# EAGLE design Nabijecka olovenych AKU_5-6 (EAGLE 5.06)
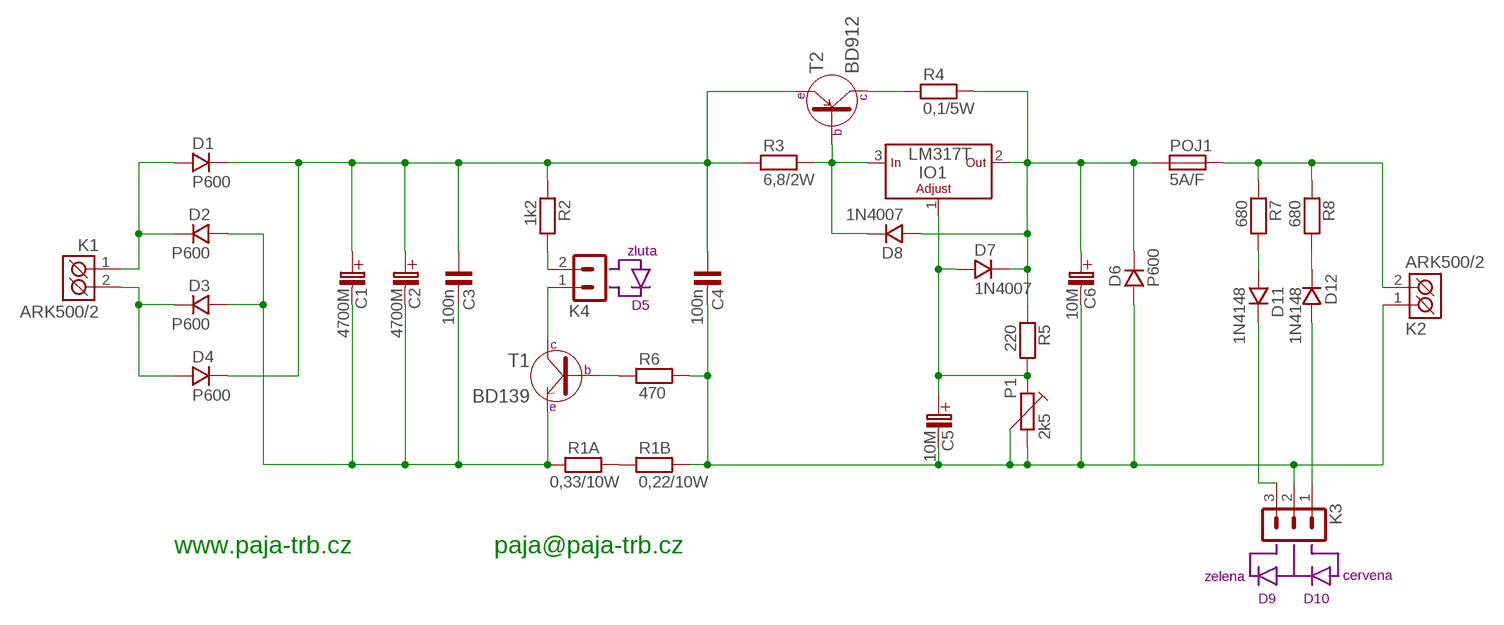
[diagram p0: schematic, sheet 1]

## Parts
C1  4700M  4700M/35V  [C_EL7,5+]
C2  4700M  4700M/35V  [C_EL7,5+]
C3  100n  C-KERAMIK_5  [C-5]
C4  100n  C-KERAMIK_5  [C-5]
C5  10M  10M/25V  [C_EL_2]
C6  10M  10M/25V  [C_EL_2]
D1  P600  [P6]
D2  P600  [P6]
D3  P600  [P6]
D4  P600  [P6]
D6  P600  [P6]
D7  1N4007  1N4007_10  [D-10]
D8  1N4007  1N4007_10  [D-10]
D11  1N4148  1N4148_7,5  [D-7,5]
D12  1N4148  1N4148_7,5  [D-7,5]
IO1  LM317T  [TO-220S]
K1  ARK500/2  [ARK500/2]
K2  ARK500/2  [ARK500/2]
K3  PSH02-03P  [PSH02-03]
K4  PSH02-02P  [PSH02-02]
P1  2k5  PT-10_V-LEZ  [PT10V]
POJ1  5A/F  PO_SHH  [POJ_SHH]
R1A  0,33/10W  R__10W  [R-_10W]
R1B  0,22/10W  R__10W  [R-_10W]
R2  1k2  R_7,5  [R-7,5]
R3  6,8/2W  R__2W  [R-_2W]
R4  0,1/5W  R__5W  [R-_5W]
R5  220  R_7,5  [R-7,5]
R6  470  R_7,5  [R-7,5]
R7  680  R_7,5  [R-7,5]
R8  680  R_7,5  [R-7,5]
T1  BD139  [TO-126S]
T2  BD912  [TO-220S]

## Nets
+BAT: K2.2(K2) POJ1.P1 R7.1 R8.1
GND: C4.2 C5.C-(C_EL-) C6.C-(C_EL-) D6.A K2.1(K1) K3.2 P1.2 P1.3 R1B.2 R6.2
MINUS: C1.C-(C_EL-) C2.C-(C_EL-) C3.2 D2.A D3.A R1A.1 T1.1(E)
N$1: D1.A D2.K K1.1(K1)
N$2: D3.K D4.A K1.2(K2)
N$5: K4.2 R2.2
N$6: R6.1 T1.3(B)
N$7: R1A.2 R1B.1
N$8: K4.1 T1.2(C)
N$10: R4.1 T2.2(C)
N$11: C6.C+(C_EL+) D6.K D7.K D8.A IO1.2(OUT) POJ1.L1 R4.2 R5.1
N$12: D8.K IO1.3(IN) R3.2 T2.1(B)
N$13: D11.K K3.3
N$14: C5.C+(C_EL+) D7.A IO1.1(ADJ) P1.1 R5.2
N$15: D12.A K3.1
N$16: D12.K R8.2
N$17: D11.A R7.2
PLUS: C1.C+(C_EL+) C2.C+(C_EL+) C3.1 C4.1 D1.K D4.K R2.1 R3.1 T2.3(E)

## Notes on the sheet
- zluta
- D5
- www.paja-trb.cz | paja@paja-trb.cz
- zelena
- cervena
- D9 | D10

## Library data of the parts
C1 C2 = #PaJa_C-el:4700M/35V
C3 C4 = #PaJa_18:C-KERAMIK: Kondenzator - keramicky
C5 C6 = #PaJa_C-el:10M/25V
D1-D4 D6 = #PaJa_18:P600?: Dioda - usmernovaci, 6A, az 10000V
D7 D8 = #PaJa_18:1N4007: Usmernovaci dioda - 1A, 1000V
D11 D12 = #PaJa_18:1N4148: Univerzalni dioda - 0,15A, 75V
IO1 = #PaJa_18:LM317T: Stabilizator - s nastavitelnym napetim - 1,5A
K1 K2 = #PaJa_18:ARK500/2: Svorkovnice - roztec 5mm - dvojita
K3 = #PaJa_18:PSH02-03: Konektory se zamkem - vidlice - 3pin
K4 = #PaJa_18:PSH02-02: Konektory se zamkem - vidlice - 2pin
P1 = #PaJa_18:PT-10: Trimr - 10,3mm
POJ1 = #PaJa_18:PO_SHH: Pojistkove pouzdro
R1A R1B R2-R8 = #PaJa_18:R: Rezistor
T1 = #PaJa_18:BD139: Tranzistor NPN - Vykonovy - Ic=1,5A
T2 = #PaJa_18:BD912: Tranzistor PNP - Vykonovy - Ic=15A

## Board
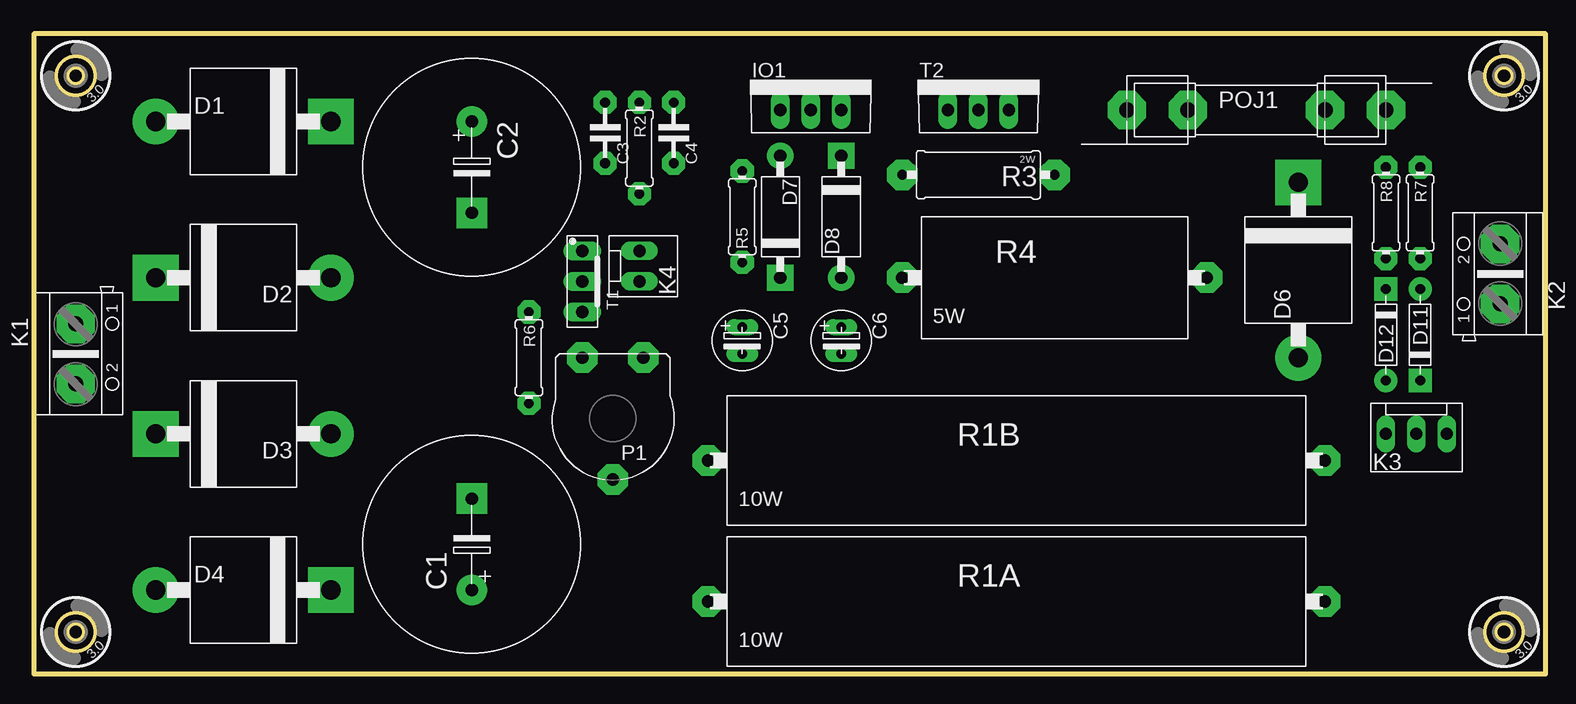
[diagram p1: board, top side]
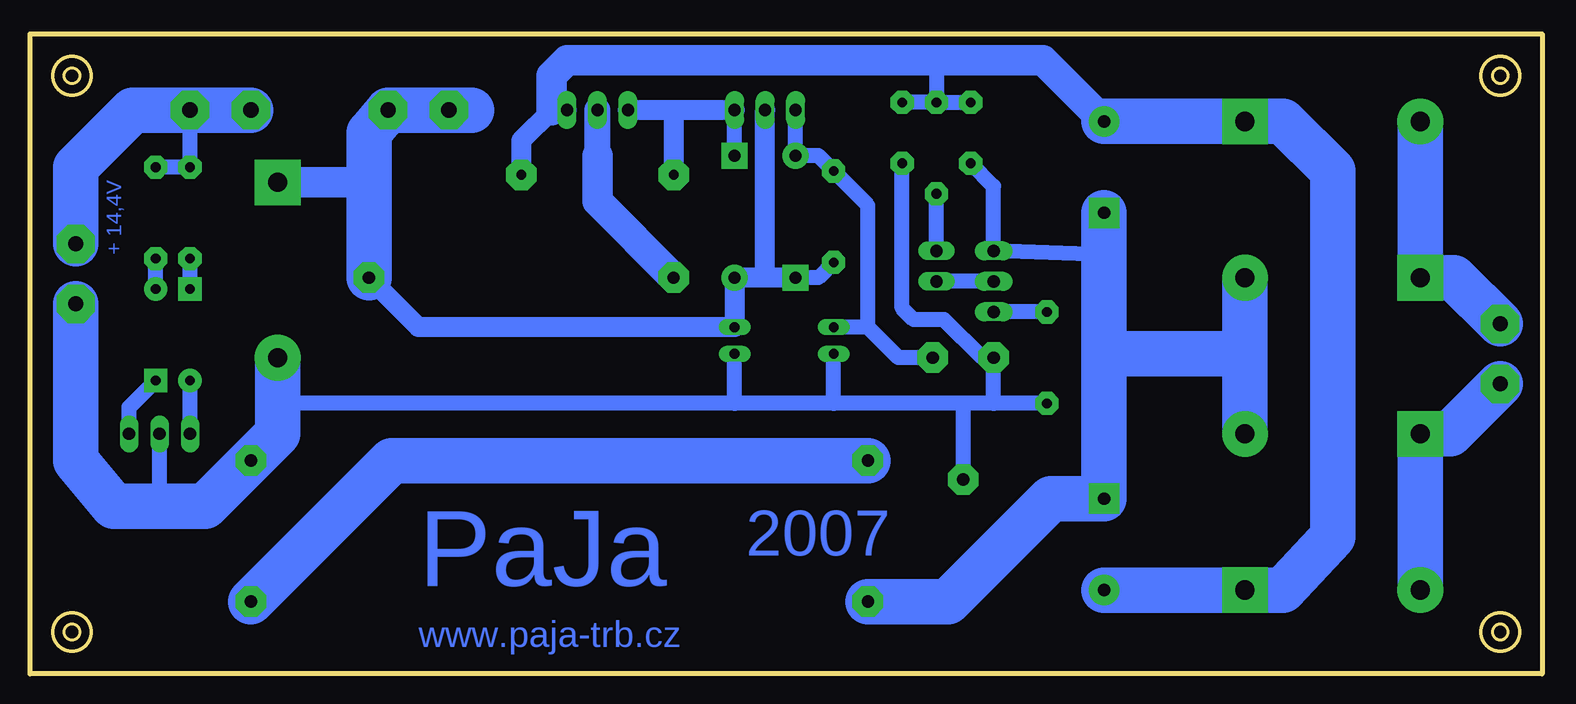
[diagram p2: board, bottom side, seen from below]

Size 126.03 x 53.33 mm. Coordinates in mm from the lower left corner, seen from the top.
Outline: 0,0 126.03,0 126.03,53.33 0,53.33 0,0
Copper layers (1*16): Top 0.035mm / dielectric 1.5mm / Bottom 0.035mm
Design rules "default": minimum track width 10mil, minimum drill 24mil, track to track 8mil, track to pad 8mil, pad to pad 8mil, via to via 8mil, smd to smd 8mil, copper to edge 40mil, drill to drill 8mil, minimum pad ring 10mil, minimum via ring 8mil, stop-mask expansion 4mil, vias tented up to drill 0mil, thermal gap 10mil
Holes 3.2 mm at 3.49,3.49 3.49,49.85 122.56,49.85 122.56,3.49

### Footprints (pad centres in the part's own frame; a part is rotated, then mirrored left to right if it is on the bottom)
C_EL7,5+ = drill 1.016 pad 2.54 round: C+ -3.81,0 | drill 1.016 pad 2.54 square: C- 3.81,0
C-5 = drill 0.813 pad 1.93 octagon: 1 -2.54,0; 2 2.54,0
C_EL_2 = drill 0.813 pad 1.27 long: C+ 0,0; C- 2.223,0
P6 = drill 1.6 pad 3.81 round: A -7.303,0 | drill 1.6 pad 3.81 square: K 7.303,0
D-10 = drill 1.016 pad 2.184 round: A -5.08,0 | drill 1.016 pad 2.184 square: K 5.08,0
D-7,5 = drill 0.813 pad 1.93 round: A -3.81,0 | drill 0.813 pad 1.93 square: K 3.81,0
TO-220S = drill 1.016 pad 1.6 long: 1 -2.54,0; 2 0,0; 3 2.54,0
ARK500/2 = drill 1.27 pad 3.2 octagon: 1 -2.5,0; 2 2.5,0
PSH02-03 = drill 1.016 pad 1.422 long: 1 -2.54,0; 2 0,0; 3 2.54,0
PSH02-02 = drill 1.016 pad 1.422 long: 1 0,0; 2 2.54,0
PT10V = drill 1.016 pad 2.54 octagon: 1 -2.54,-5.08; 2 2.54,-5.08; 3 0,5.08
POJ_SHH = drill 1.27 pad 3.2 octagon: L1 -10.795,0; L2 -5.715,0; P1 10.795,0; P2 5.715,0
R-_10W = drill 1.016 pad 2.54 octagon: 1 -25.718,0; 2 25.718,0
R-7,5 = drill 0.813 pad 1.93 octagon: 1 -3.81,0; 2 3.81,0
R-_2W = drill 0.813 pad 2.54 octagon: 1 -6.35,0; 2 6.35,0
R-_5W = drill 1.016 pad 2.54 octagon: 1 -12.7,0; 2 12.7,0
TO-126S = drill 1.016 pad 1.6 long: 1 -2.54,0; 2 0,0; 3 2.54,0
HOLE_3,0 = hole 3.2: 0,0

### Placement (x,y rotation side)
C1  36.51,10.79 90 top
C2  36.51,42.23 270 top
C3  47.62,45.09 270 top
C4  53.34,45.09 270 top
C5  59.05,28.89 270 top
C6  67.31,28.89 270 top
D1  17.46,46.04 0 top
D2  17.46,33.02 180 top
D3  17.46,20 180 top
D4  17.46,6.99 0 top
D6  105.41,33.66 90 top
D7  62.23,38.1 270 top
D8  67.31,38.1 90 top
D11  115.57,28.26 270 top
D12  112.71,28.26 90 top
IO1  64.77,46.99 0 top
K1  3.49,26.67 270 top
K2  122.24,33.34 90 top
K3  115.25,20 0 top
K4  50.48,32.7 90 top
P1  48.26,21.27 180 top
POJ1  101.92,46.99 0 top
R1A  81.92,6.03 0 top
R1B  81.92,17.78 0 top
R2  50.48,43.81 270 top
R3  78.74,41.59 180 top
R4  85.09,33.02 0 top
R5  59.05,38.1 90 top
R6  41.27,26.35 270 top
R7  115.57,38.42 270 top
R8  112.71,38.42 270 top
T1  45.72,32.7 270 top
T2  78.74,46.99 0 top
U$1  [HOLE_3,0]  3.49,3.49 0 top
U$2  [HOLE_3,0]  3.49,49.85 0 top
U$3  [HOLE_3,0]  122.56,49.85 0 top
U$4  [HOLE_3,0]  122.56,3.49 0 top

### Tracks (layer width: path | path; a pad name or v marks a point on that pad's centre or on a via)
+BAT
  Bottom 1.27: R7.1 R8.1 POJ1.P1
  Bottom 3.81: 107.63,46.99 POJ1.P1 117.47,46.99 122.24,42.23 K2.2
GND
  Bottom 1.27: 48.26,22.54 59.05,22.54 | 59.05,22.54 67.31,22.54 | 67.31,22.54 105.41,22.54 | 48.26,22.54 P1.3 | 115.25,13.97 K3.2 | C4.2 53.34,30.48 52.39,29.53 49.85,29.53 46.67,26.35 P1.2 45.72,22.54 | R6.2 45.72,22.54 | 45.72,22.54 48.26,22.54 | 59.05,22.54 C5.C- | 67.31,22.54 C6.C-
  Bottom 3.81: D6.A 105.41,22.54 105.41,20 R1B.2 111.44,13.97 115.25,13.97 119.06,13.97 122.24,17.78 K2.1
MINUS
  Bottom 1.27: 36.51,34.92 T1.1 45.72,40.64 C3.2
  Bottom 3.81: D3.A 24.77,26.67 | 24.77,26.67 D2.A | 36.51,26.67 C1.C- 40.96,14.61 49.53,6.03 R1A.1 | 36.51,26.67 36.51,34.92 C2.C- | 24.77,26.67 36.51,26.67
N$1
  Bottom 3.81: D1.A D2.K 7.34,33.02 K1.1
N$2
  Bottom 3.81: D4.A D3.K 7.66,20 K1.2
N$5
  Bottom 1.27: K4.2 R2.2
N$6
  Bottom 1.27: R6.1 T1.3
N$7
  Bottom 3.81: R1A.2 95.89,17.78 R1B.1
N$8
  Bottom 1.27: T1.2 K4.1
N$10
  Bottom 2.184: 78.74,43.18 T2.2
  Bottom 2.54: R4.1 78.74,39.37 78.74,43.18
N$11
  Bottom 1.27: R5.1 60.33,33.02 D7.K
  Bottom 1.676: D7.K 64.77,33.02 | 64.77,33.02 D8.A C6.C+ 93.66,28.89 R4.2 | 64.77,33.02 IO1.2
  Bottom 2.54: 97.79,40.96 D6.K
  Bottom 3.81: R4.2 97.79,40.96 97.79,45.09 96.2,46.99 POJ1.L1 89.22,46.99
N$12
  Bottom 1.27: D8.K IO1.3
  Bottom 1.676: IO1.3 72.39,46.99 | 72.39,46.99 T2.1 | 72.39,46.99 R3.2
N$13
  Bottom 1.27: K3.3 117.79,22.23 D11.K
N$14
  Bottom 1.27: IO1.1 D7.A 60.33,43.18 R5.2 56.2,39.05 56.2,28.89 | 56.2,28.89 53.66,26.35 P1.1 | 56.2,28.89 C5.C+
N$15
  Bottom 1.27: K3.1 D12.A
N$16
  Bottom 1.27: D12.K R8.2
N$17
  Bottom 1.27: D11.A R7.2
PLUS
  Bottom 1.27: 50.48,51.12 R2.1 | R2.1 C3.1 | R2.1 C4.1
  Bottom 1.676: R3.1 85.09,44.45 82.55,46.99 T2.3
  Bottom 2.54: C2.C+ 41.59,51.12 50.48,51.12 81.28,51.12 82.55,49.85 82.55,46.99
  Bottom 3.81: C2.C+ D1.K 21.59,46.04 17.46,41.91 17.46,11.43 21.59,6.99 D4.K C1.C+

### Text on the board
Bottom: + 14,4V | 2007 | PaJa | www.paja-trb.cz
